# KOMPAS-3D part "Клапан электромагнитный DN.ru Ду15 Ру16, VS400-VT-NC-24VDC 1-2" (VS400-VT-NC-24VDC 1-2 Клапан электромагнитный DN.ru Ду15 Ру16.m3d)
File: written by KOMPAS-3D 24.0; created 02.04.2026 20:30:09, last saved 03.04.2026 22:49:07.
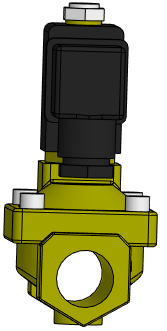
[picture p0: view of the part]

Document properties: Автор: artio; Полное имя файла: C:\Users\artio\OneDrive\Рабочий стол\Клапан электромагнитный DN.ru\VS400-VT-NC\VS400-VT-NC-24VDC 1-2 Клапан электромагнитный DN.ru Ду15 Ру16.m3d

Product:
- Body: Тело 1  | qty 1
    Масса: 1.030062
- Part/product: Клапан электромагнитный DN.ru Ду15 Ру16  | designation VS400-VT-NC-24VDC 1-2
    Масса: 0.759
    Раздел спецификации: Прочие изделия
    Примечание: D130-04733
    additional columns: ef56311e-7521-43dc-8291-0e6108b3d81d; VS400-ET-NC-220VAC 1-2; artio; c; Шероховатость не задана; Да

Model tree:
1. Операция без истории:1

Expressions: VS400-VT-NC-24VDC 1-2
